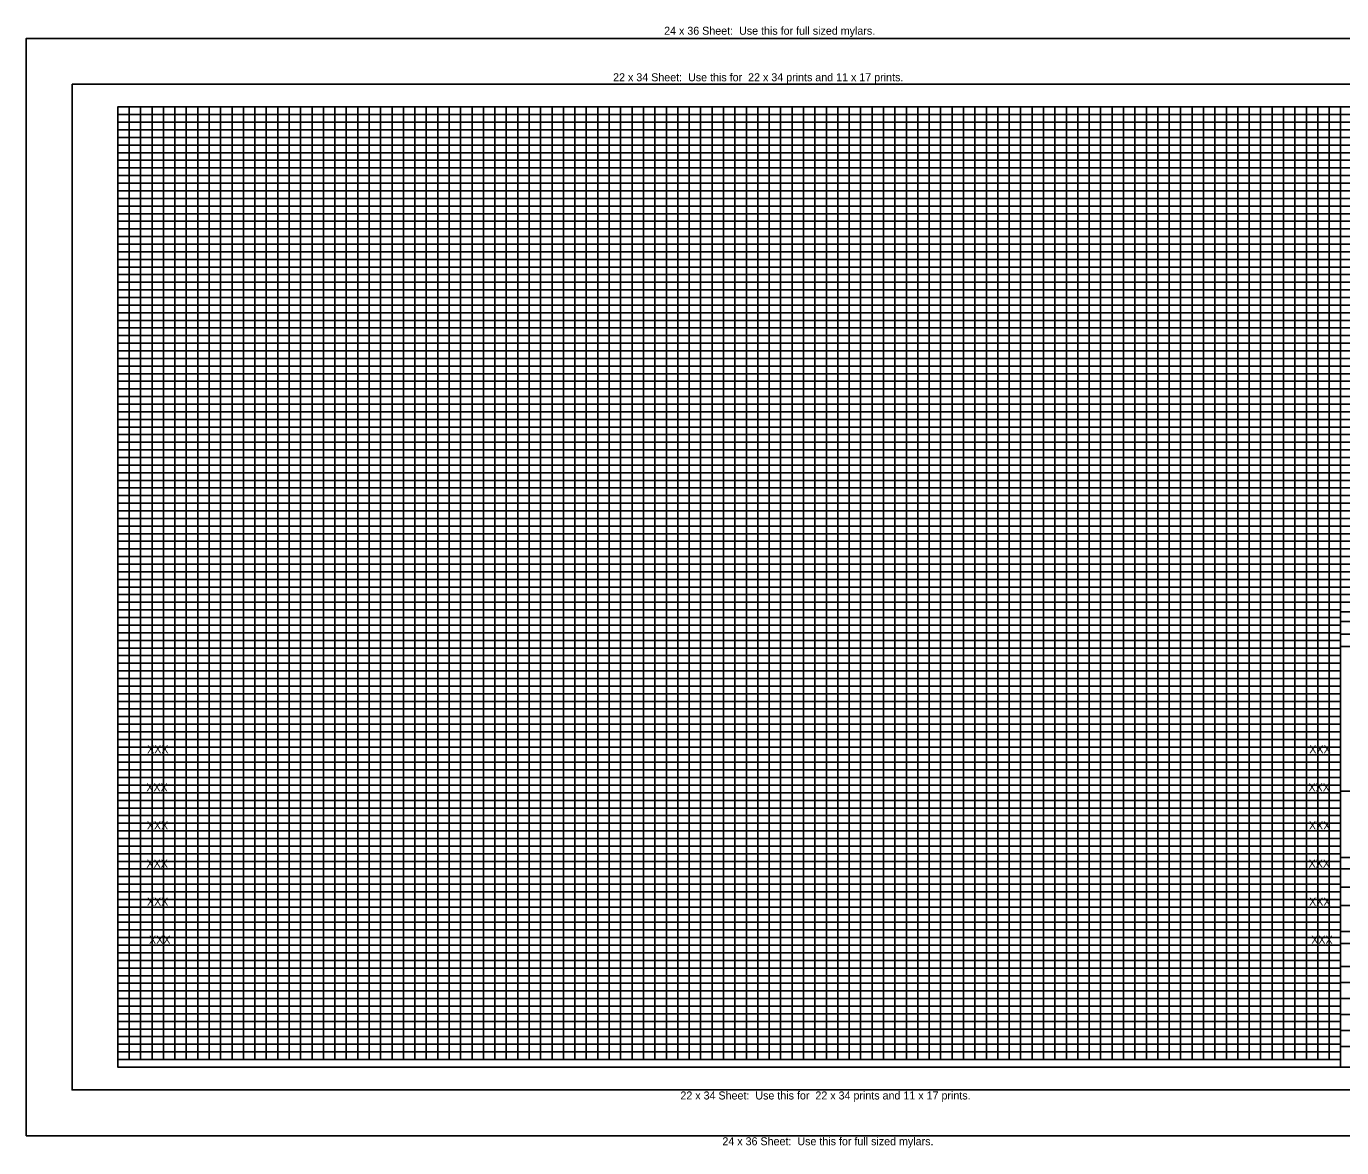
# Model space of a CAD drawing. Extents: x -2311 to -1444, y -1548 to -1045.
# Drawn here: x -2311 to -1735, y -1548 to -1057 of the extents above; entities that cross this region are included whole.
import ezdxf

# ---------------------------------------------------------------- set-up
doc = ezdxf.new("R2010")
doc.units = 0
for name, color, linetype in [('G_BORDER', 7, 'Continuous'), ('G_GRID_MAJOR', 7, 'Continuous'), ('G_GRID_MINOR', 7, 'Continuous'), ('G_SHEET_EDGE', 7, 'Continuous')]:
    doc.layers.add(name, color=color, linetype=linetype)

msp = doc.modelspace()

# ---------------------------------------------------------------- linework, layer by layer
at = {"layer": 'G_BORDER'}
for p, q in [((-1735.65, -1313.3), (-1620.65, -1313.3)), ((-1735.65, -1317.5), (-1620.65, -1317.5)), ((-1735.65, -1323), (-1620.65, -1323)), ((-1735.65, -1425.77), (-1685.65, -1425.77)), ((-1735.65, -1433.77), (-1685.65, -1433.77)), ((-1620.65, -1468.44), (-1735.65, -1468.44)), ((-1620.65, -1475.44), (-1735.65, -1475.44)), ((-1620.65, -1482.44), (-1735.65, -1482.44)), ((-1620.65, -1489.44), (-1735.65, -1489.44)), ((-1620.65, -1496.44), (-1735.65, -1496.44)), ((-1620.65, -1503.44), (-1735.65, -1503.44))]:
    msp.add_line(p, q, dxfattribs=at)
for points in [[(-1620.65, -1092.44), (-2270.65, -1092.44), (-2270.65, -1512.44), (-1620.65, -1512.44)], [(-1735.65, -1309.1), (-1620.65, -1309.1), (-1620.65, -1328.5), (-1735.65, -1328.5)], [(-1735.65, -1328.5), (-1620.65, -1328.5), (-1620.65, -1391.77), (-1735.65, -1391.77)], [(-1735.65, -1391.77), (-1685.65, -1391.77), (-1685.65, -1420.77), (-1735.65, -1420.77)], [(-1735.65, -1420.77), (-1685.65, -1420.77), (-1685.65, -1441.77), (-1735.65, -1441.77)], [(-1735.65, -1441.77), (-1620.65, -1441.77), (-1620.65, -1453.19), (-1735.65, -1453.19)], [(-1735.65, -1453.19), (-1672.9, -1453.19), (-1672.9, -1458.44), (-1735.65, -1458.44)], [(-1735.65, -1458.44), (-1620.65, -1458.44), (-1620.65, -1512.44), (-1735.65, -1512.44)]]:
    msp.add_lwpolyline(points, close=True, dxfattribs=at)
at = {"layer": 'G_GRID_MAJOR'}
for p, q in [((-2235.65, -1509.1), (-2235.65, -1092.44)), ((-2185.65, -1509.1), (-2185.65, -1092.44)), ((-2135.65, -1509.1), (-2135.65, -1092.44)), ((-2085.65, -1509.1), (-2085.65, -1092.44)), ((-2035.65, -1509.1), (-2035.65, -1092.44)), ((-1985.65, -1509.1), (-1985.65, -1092.44)), ((-1935.65, -1509.1), (-1935.65, -1092.44)), ((-1885.65, -1509.1), (-1885.65, -1092.44)), ((-1835.65, -1509.1), (-1835.65, -1092.44)), ((-1785.65, -1509.1), (-1785.65, -1092.44)), ((-1735.65, -1309.1), (-1735.65, -1092.44)), ((-1620.65, -1109.11), (-2270.65, -1109.11)), ((-1620.65, -1125.77), (-2270.65, -1125.77)), ((-1620.65, -1142.44), (-2270.65, -1142.44)), ((-1620.65, -1159.11), (-2270.65, -1159.11)), ((-1620.65, -1175.77), (-2270.65, -1175.77)), ((-1620.65, -1192.44), (-2270.65, -1192.44)), ((-1620.65, -1209.11), (-2270.65, -1209.11)), ((-1620.65, -1225.77), (-2270.65, -1225.77)), ((-1620.65, -1242.44), (-2270.65, -1242.44)), ((-1620.65, -1259.11), (-2270.65, -1259.11)), ((-1620.65, -1275.77), (-2270.65, -1275.77)), ((-1620.65, -1292.44), (-2270.65, -1292.44)), ((-1735.65, -1309.1), (-2270.65, -1309.1)), ((-1735.65, -1325.77), (-2270.65, -1325.77)), ((-1735.65, -1342.44), (-2270.65, -1342.44)), ((-1735.65, -1359.1), (-2270.65, -1359.1)), ((-1735.65, -1375.77), (-2270.65, -1375.77)), ((-1735.65, -1392.44), (-2270.65, -1392.44)), ((-1735.65, -1409.1), (-2270.65, -1409.1)), ((-1735.65, -1425.77), (-2270.65, -1425.77)), ((-1735.65, -1442.44), (-2270.65, -1442.44)), ((-1735.65, -1459.1), (-2270.65, -1459.1)), ((-1735.65, -1475.77), (-2270.65, -1475.77)), ((-1735.65, -1492.44), (-2270.65, -1492.44)), ((-1735.65, -1509.1), (-2270.65, -1509.1))]:
    msp.add_line(p, q, dxfattribs=at)
at = {"layer": 'G_GRID_MINOR'}
for p, q in [((-2270.65, -1509.1), (-2270.65, -1093.1)), ((-2265.65, -1509.1), (-2265.65, -1092.44)), ((-2260.65, -1509.1), (-2260.65, -1092.44)), ((-2255.65, -1509.1), (-2255.65, -1092.44)), ((-2250.65, -1509.1), (-2250.65, -1092.44)), ((-2245.65, -1509.1), (-2245.65, -1092.44)), ((-2240.65, -1509.1), (-2240.65, -1092.44)), ((-2230.65, -1509.1), (-2230.65, -1092.44)), ((-2225.65, -1509.1), (-2225.65, -1092.44)), ((-2220.65, -1509.1), (-2220.65, -1092.44)), ((-2215.65, -1509.1), (-2215.65, -1092.44)), ((-2210.65, -1509.1), (-2210.65, -1092.44)), ((-2205.65, -1509.1), (-2205.65, -1092.44)), ((-2200.65, -1509.1), (-2200.65, -1092.44)), ((-2195.65, -1509.1), (-2195.65, -1092.44)), ((-2190.65, -1509.1), (-2190.65, -1092.44)), ((-2180.65, -1509.1), (-2180.65, -1092.44)), ((-2175.65, -1509.1), (-2175.65, -1092.44)), ((-2170.65, -1509.1), (-2170.65, -1092.44)), ((-2165.65, -1509.1), (-2165.65, -1092.44)), ((-2160.65, -1509.1), (-2160.65, -1092.44)), ((-2155.65, -1509.1), (-2155.65, -1092.44)), ((-2150.65, -1509.1), (-2150.65, -1092.44)), ((-2145.65, -1509.1), (-2145.65, -1092.44)), ((-2140.65, -1509.1), (-2140.65, -1092.44)), ((-2130.65, -1509.1), (-2130.65, -1092.44)), ((-2125.65, -1509.1), (-2125.65, -1092.44)), ((-2120.65, -1509.1), (-2120.65, -1092.44)), ((-2115.65, -1509.1), (-2115.65, -1092.44)), ((-2110.65, -1509.1), (-2110.65, -1092.44)), ((-2105.65, -1509.1), (-2105.65, -1092.44)), ((-2100.65, -1509.1), (-2100.65, -1092.44)), ((-2095.65, -1509.1), (-2095.65, -1092.44)), ((-2090.65, -1509.1), (-2090.65, -1092.44)), ((-2080.65, -1509.1), (-2080.65, -1092.44)), ((-2075.65, -1509.1), (-2075.65, -1092.44)), ((-2070.65, -1509.1), (-2070.65, -1092.44)), ((-2065.65, -1509.1), (-2065.65, -1092.44)), ((-2060.65, -1509.1), (-2060.65, -1092.44)), ((-2055.65, -1509.1), (-2055.65, -1092.44)), ((-2050.65, -1509.1), (-2050.65, -1092.44)), ((-2045.65, -1509.1), (-2045.65, -1092.44)), ((-2040.65, -1509.1), (-2040.65, -1092.44)), ((-2030.65, -1509.1), (-2030.65, -1092.44)), ((-2025.65, -1509.1), (-2025.65, -1092.44)), ((-2020.65, -1509.1), (-2020.65, -1092.44)), ((-2015.65, -1509.1), (-2015.65, -1092.44)), ((-2010.65, -1509.1), (-2010.65, -1092.44)), ((-2005.65, -1509.1), (-2005.65, -1092.44)), ((-2000.65, -1509.1), (-2000.65, -1092.44)), ((-1995.65, -1509.1), (-1995.65, -1092.44)), ((-1990.65, -1509.1), (-1990.65, -1092.44)), ((-1980.65, -1509.1), (-1980.65, -1092.44)), ((-1975.65, -1509.1), (-1975.65, -1092.44)), ((-1970.65, -1509.1), (-1970.65, -1092.44)), ((-1965.65, -1509.1), (-1965.65, -1092.44)), ((-1960.65, -1509.1), (-1960.65, -1092.44)), ((-1955.65, -1509.1), (-1955.65, -1092.44)), ((-1950.65, -1509.1), (-1950.65, -1092.44)), ((-1945.65, -1509.1), (-1945.65, -1092.44)), ((-1940.65, -1509.1), (-1940.65, -1092.44)), ((-1930.65, -1509.1), (-1930.65, -1092.44)), ((-1925.65, -1509.1), (-1925.65, -1092.44)), ((-1920.65, -1509.1), (-1920.65, -1092.44)), ((-1915.65, -1509.1), (-1915.65, -1092.44)), ((-1910.65, -1509.1), (-1910.65, -1092.44)), ((-1905.65, -1509.1), (-1905.65, -1092.44)), ((-1900.65, -1509.1), (-1900.65, -1092.44)), ((-1895.65, -1509.1), (-1895.65, -1092.44)), ((-1890.65, -1509.1), (-1890.65, -1092.44)), ((-1880.65, -1509.1), (-1880.65, -1092.44)), ((-1875.65, -1509.1), (-1875.65, -1092.44)), ((-1870.65, -1509.1), (-1870.65, -1092.44)), ((-1865.65, -1509.1), (-1865.65, -1092.44)), ((-1860.65, -1509.1), (-1860.65, -1092.44)), ((-1855.65, -1509.1), (-1855.65, -1092.44)), ((-1850.65, -1509.1), (-1850.65, -1092.44)), ((-1845.65, -1509.1), (-1845.65, -1092.44)), ((-1840.65, -1509.1), (-1840.65, -1092.44)), ((-1830.65, -1509.1), (-1830.65, -1092.44)), ((-1825.65, -1509.1), (-1825.65, -1092.44)), ((-1820.65, -1509.1), (-1820.65, -1092.44)), ((-1815.65, -1509.1), (-1815.65, -1092.44)), ((-1810.65, -1509.1), (-1810.65, -1092.44)), ((-1805.65, -1509.1), (-1805.65, -1092.44)), ((-1800.65, -1509.1), (-1800.65, -1092.44)), ((-1795.65, -1509.1), (-1795.65, -1092.44)), ((-1790.65, -1509.1), (-1790.65, -1092.44)), ((-1780.65, -1509.1), (-1780.65, -1092.44)), ((-1775.65, -1509.1), (-1775.65, -1092.44)), ((-1770.65, -1509.1), (-1770.65, -1092.44)), ((-1765.65, -1509.1), (-1765.65, -1092.44)), ((-1760.65, -1509.1), (-1760.65, -1092.44)), ((-1755.65, -1509.1), (-1755.65, -1092.44)), ((-1750.65, -1509.1), (-1750.65, -1092.44)), ((-1745.65, -1509.1), (-1745.65, -1092.44)), ((-1740.65, -1509.1), (-1740.65, -1092.44)), ((-1620.65, -1095.77), (-2270.65, -1095.77)), ((-1620.65, -1099.11), (-2270.65, -1099.11)), ((-1620.65, -1102.44), (-2270.65, -1102.44)), ((-1620.65, -1105.77), (-2270.65, -1105.77)), ((-1620.65, -1112.44), (-2270.65, -1112.44)), ((-1620.65, -1115.77), (-2270.65, -1115.77)), ((-1620.65, -1119.11), (-2270.65, -1119.11)), ((-1620.65, -1122.44), (-2270.65, -1122.44)), ((-1620.65, -1129.11), (-2270.65, -1129.11)), ((-1620.65, -1132.44), (-2270.65, -1132.44)), ((-1620.65, -1135.77), (-2270.65, -1135.77)), ((-1620.65, -1139.11), (-2270.65, -1139.11)), ((-1620.65, -1145.77), (-2270.65, -1145.77)), ((-1620.65, -1149.11), (-2270.65, -1149.11)), ((-1620.65, -1152.44), (-2270.65, -1152.44)), ((-1620.65, -1155.77), (-2270.65, -1155.77)), ((-1620.65, -1162.44), (-2270.65, -1162.44)), ((-1620.65, -1165.77), (-2270.65, -1165.77)), ((-1620.65, -1169.11), (-2270.65, -1169.11)), ((-1620.65, -1172.44), (-2270.65, -1172.44)), ((-1620.65, -1179.11), (-2270.65, -1179.11)), ((-1620.65, -1182.44), (-2270.65, -1182.44)), ((-1620.65, -1185.77), (-2270.65, -1185.77)), ((-1620.65, -1189.11), (-2270.65, -1189.11)), ((-1620.65, -1195.77), (-2270.65, -1195.77)), ((-1620.65, -1199.11), (-2270.65, -1199.11)), ((-1620.65, -1202.44), (-2270.65, -1202.44)), ((-1620.65, -1205.77), (-2270.65, -1205.77)), ((-1620.65, -1212.44), (-2270.65, -1212.44)), ((-1620.65, -1215.77), (-2270.65, -1215.77)), ((-1620.65, -1219.11), (-2270.65, -1219.11)), ((-1620.65, -1222.44), (-2270.65, -1222.44)), ((-1620.65, -1229.11), (-2270.65, -1229.11)), ((-1620.65, -1232.44), (-2270.65, -1232.44)), ((-1620.65, -1235.77), (-2270.65, -1235.77)), ((-1620.65, -1239.11), (-2270.65, -1239.11)), ((-1620.65, -1245.77), (-2270.65, -1245.77)), ((-1620.65, -1249.11), (-2270.65, -1249.11)), ((-1620.65, -1252.44), (-2270.65, -1252.44)), ((-1620.65, -1255.77), (-2270.65, -1255.77)), ((-1620.65, -1262.44), (-2270.65, -1262.44)), ((-1620.65, -1265.77), (-2270.65, -1265.77)), ((-1620.65, -1269.11), (-2270.65, -1269.11)), ((-1620.65, -1272.44), (-2270.65, -1272.44)), ((-1620.65, -1279.11), (-2270.65, -1279.11)), ((-1620.65, -1282.44), (-2270.65, -1282.44)), ((-1620.65, -1285.77), (-2270.65, -1285.77)), ((-1620.65, -1289.11), (-2270.65, -1289.11)), ((-1620.65, -1295.77), (-2270.65, -1295.77)), ((-1620.65, -1299.11), (-2270.65, -1299.11)), ((-1620.65, -1302.44), (-2270.65, -1302.44)), ((-1620.65, -1305.77), (-2270.65, -1305.77)), ((-1735.65, -1312.44), (-2270.65, -1312.44)), ((-1735.65, -1315.77), (-2270.65, -1315.77)), ((-1735.65, -1319.1), (-2270.65, -1319.1)), ((-1735.65, -1322.44), (-2270.65, -1322.44)), ((-1735.65, -1329.11), (-2270.65, -1329.11)), ((-1735.65, -1332.44), (-2270.65, -1332.44)), ((-1735.65, -1335.77), (-2270.65, -1335.77)), ((-1735.65, -1339.1), (-2270.65, -1339.1)), ((-1735.65, -1345.77), (-2270.65, -1345.77)), ((-1735.65, -1349.1), (-2270.65, -1349.1)), ((-1735.65, -1352.44), (-2270.65, -1352.44)), ((-1735.65, -1355.77), (-2270.65, -1355.77)), ((-1735.65, -1362.44), (-2270.65, -1362.44)), ((-1735.65, -1365.77), (-2270.65, -1365.77)), ((-1735.65, -1369.1), (-2270.65, -1369.1)), ((-1735.65, -1372.44), (-2270.65, -1372.44)), ((-1735.65, -1379.1), (-2270.65, -1379.1)), ((-1735.65, -1382.44), (-2270.65, -1382.44)), ((-1735.65, -1385.77), (-2270.65, -1385.77)), ((-1735.65, -1389.1), (-2270.65, -1389.1)), ((-1735.65, -1395.77), (-2270.65, -1395.77)), ((-1735.65, -1399.1), (-2270.65, -1399.1)), ((-1735.65, -1402.44), (-2270.65, -1402.44)), ((-1735.65, -1405.77), (-2270.65, -1405.77)), ((-1735.65, -1412.44), (-2270.65, -1412.44)), ((-1735.65, -1415.77), (-2270.65, -1415.77)), ((-1735.65, -1419.1), (-2270.65, -1419.1)), ((-1735.65, -1422.44), (-2270.65, -1422.44)), ((-1735.65, -1429.1), (-2270.65, -1429.1)), ((-1735.65, -1432.44), (-2270.65, -1432.44)), ((-1735.65, -1435.77), (-2270.65, -1435.77)), ((-1735.65, -1439.1), (-2270.65, -1439.1)), ((-1735.65, -1445.77), (-2270.65, -1445.77)), ((-1735.65, -1449.1), (-2270.65, -1449.1)), ((-1735.65, -1452.44), (-2270.65, -1452.44)), ((-1735.65, -1455.77), (-2270.65, -1455.77)), ((-1735.65, -1462.44), (-2270.65, -1462.44)), ((-1735.65, -1465.77), (-2270.65, -1465.77)), ((-1735.65, -1469.1), (-2270.65, -1469.1)), ((-1735.65, -1472.44), (-2270.65, -1472.44)), ((-1735.65, -1479.1), (-2270.65, -1479.1)), ((-1735.65, -1482.44), (-2270.65, -1482.44)), ((-1735.65, -1485.77), (-2270.65, -1485.77)), ((-1735.65, -1489.1), (-2270.65, -1489.1)), ((-1735.65, -1495.77), (-2270.65, -1495.77)), ((-1735.65, -1499.1), (-2270.65, -1499.1)), ((-1735.65, -1502.44), (-2270.65, -1502.44)), ((-1735.65, -1505.77), (-2270.65, -1505.77))]:
    msp.add_line(p, q, dxfattribs=at)
at = {"layer": 'G_SHEET_EDGE'}
for points in [[(-2310.65, -1542.44), (-1590.65, -1542.44), (-1590.65, -1062.44), (-2310.65, -1062.44)], [(-2290.65, -1082.44), (-1610.65, -1082.44), (-1610.65, -1522.44), (-2290.65, -1522.44)]]:
    msp.add_lwpolyline(points, close=True, dxfattribs=at)

# ---------------------------------------------------------------- texts
at = {"layer": 'G_GRID_MAJOR'}
for p in [(-2257.8, -1375.15), (-1749.38, -1375.15), (-2258.16, -1391.81), (-1749.74, -1391.81), (-2257.94, -1408.48), (-1749.53, -1408.48), (-2258.08, -1425.15), (-1749.67, -1425.15), (-2257.87, -1441.81), (-1749.46, -1441.81), (-2256.95, -1458.48), (-1748.53, -1458.48)]:
    msp.add_text('XXX', height=3.5, dxfattribs=at).set_placement(p)
at = {"layer": 'G_SHEET_EDGE'}
for s, p in [('24 x 36 Sheet:  Use this for full sized mylars. ', (-2031.62, -1060.84)), ('22 x 34 Sheet:  Use this for  22 x 34 prints and 11 x 17 prints. ', (-2053.93, -1081.19)), ('22 x 34 Sheet:  Use this for  22 x 34 prints and 11 x 17 prints. ', (-2024.5, -1526.6)), ('24 x 36 Sheet:  Use this for full sized mylars. ', (-2006.12, -1546.63))]:
    msp.add_text(s, height=3.5, dxfattribs=at).set_placement(p)

doc.saveas('drawing.dxf')
